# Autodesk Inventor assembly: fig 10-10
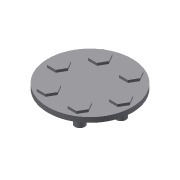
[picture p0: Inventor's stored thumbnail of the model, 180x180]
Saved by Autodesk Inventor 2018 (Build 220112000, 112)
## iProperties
Created: 2008-05
Part Number: fig 10-10
Document SubType Name: Assembly
Designer: CADCIM
Author: CADCIM
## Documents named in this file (3)
- E:\_Deepak\Inventor\Autodesk Inventor_2017_Project\Resources\Inventor_2018_Part\c10_Inv_2018\c10_inv_2018_prt\fig 10-10.iam
- E:\_Deepak\Inventor\Autodesk Inventor_2017_Project\Resources\Inventor_2018_Part\c10_Inv_2018\c10_inv_2018_prt\Part4.ipt
- E:\_Deepak\Inventor\Autodesk Inventor_2017_Project\Resources\Inventor_2018_Part\c10_Inv_2018\c10_inv_2018_prt\Part5.ipt
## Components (7 placed, 2 different names)
1. Part4:1
2. Part5:1
3. Part5:2
4. Part5:3
5. Part5:4
6. Part5:5
7. Part5:6
